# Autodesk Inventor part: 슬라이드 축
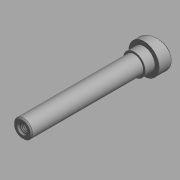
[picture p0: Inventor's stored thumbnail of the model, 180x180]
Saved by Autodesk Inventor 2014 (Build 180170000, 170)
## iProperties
Created: 2015-11
Part Number: 슬라이드 축
Document SubType Name: 모델링
Designer: mdu
Mass: 174.309 g
Surface Area: 67.586 cm^2
Volume: 21.5729 cm^3
Density: 8.08 g/cm^3
Material: 스테인리스강
Appearance: 기본값
변환 표준: STEP AP214IS
파일 이름: C:\Users\SeoGD\Desktop\?쒗뿕\異?stp
전처리기: Build: 253, Release: 2010 SP1 - Date: Wed 07/29/2009
전송 단위: 밀리미터
불확실성: 0.01
Author: mdu
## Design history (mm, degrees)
sketch "스케치1"
  geometry: L1 (0, 100)-(7.5, 100); L2 (7.5, 100)-(7.5, 0); L3 (7.5, 0)-(12.5, 0); L4 (12.5, 0)-(12.5, -17); L5 (12.5, -17)-(0, -17); L6 (0, -17)-(0, 100); 1 further point
  constraints: 12 end point, 2 parallel, 2 point on line, 1 perpendicular, 1 vertical
  dimensions: "d0" = 100 distance from line of L1 point (0, 0); "d1" = 15 diameter of L2 L6; "d2" = 25 diameter of L4 L6; "d3" = 17 distance of L3.end L4.end
revolve "회전1" sketch "스케치1" stored, may be unused: angle "d4" = 90 deg
sketch "스케치2"
  geometry: L1 (12.5, 0)-(12.5, -17) reference; L2 (-12.5, -17)-(12.5, -17) reference; L3 (-12.5, 0)-(-12.5, -17) reference; L4 (12.5, -5)-(-12.5, -11.699); L5 (-12.5, 0)-(12.5, 0) reference; 1 further point
  constraints: 2 end point, 2 point on line
  dimensions: "d5" = 75 deg angle of L1 L4; "d6" = 5 distance from line of L4.start L5
extrude "돌출1" cut sketch "스케치2" stored distance "d7" = 10; taper "d8" = 0 deg
chamfer "모따기1" distance "d9" = 1; stored, may be unused: second distance "d10" = 2, angle "d11" = 45 deg
fillet "모깎기1" dims "d12" = 0.5
hole "구멍1" diameter "d15" = 6.647; stored, may be unused: countersink angle "d19" = 90 deg, drill point angle "d21" = 118 deg; dims "d13" = 10, "d14" = 10, "d16" = 17, "d17" = 4, "d18" = 2, "d20" = 20
chamfer "모따기2" distance "d22" = 1; stored, may be unused: second distance "d23" = 2, angle "d24" = 45 deg
sketch "스케치3"
  geometry: C1 r 9 at (0, 0); 1 further point
  constraints: 1 centre point, 1 coincident
  dimensions: "d25" = 18 diameter of C1
extrude "돌출2" join sketch "스케치3" distance "d26" = 8; taper "d27" = 0 deg
node "솔리드1"
node "솔리드 본체"
node "곡면 본체"
node "솔리드2"
